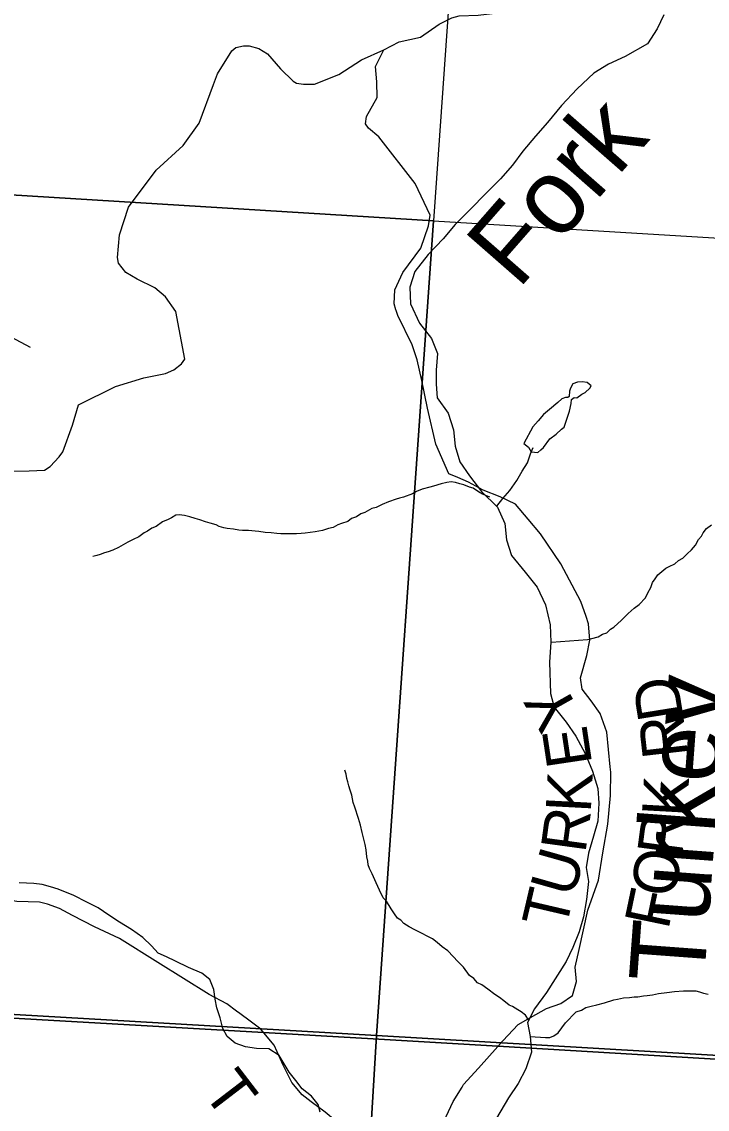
# Model space of a CAD drawing. Extents: x 0 to 34, y 0 to 22.
# Drawn here: x 7.274 to 8.137, y 16.183 to 17.554 of the extents above; entities that cross this region are included whole.
import ezdxf

# ---------------------------------------------------------------- set-up
doc = ezdxf.new("R2010")
doc.units = 0
for name, color, linetype in [('GM_X_Corporation', 7, 'Continuous'), ('GM_X_County_Road', 7, 'Continuous'), ('GM_X_Minor_Lake', 7, 'Continuous'), ('GM_X_Minor_River', 7, 'Continuous'), ('GM_X_Minor_River_Text', 7, 'Continuous'), ('GM_X_Township_Road', 7, 'Continuous'), ('GM_X_Township_Road_Text', 7, 'Continuous')]:
    doc.layers.add(name, color=color, linetype=linetype)

msp = doc.modelspace()

# ---------------------------------------------------------------- linework, layer by layer
at = {"layer": 'GM_X_Corporation'}
for points in [[(8.9, 16.2015), (8.9, 20.2763), (8.59, 20.3005), (8.3805, 20.3169), (8.0028, 20.34), (6.9032, 20.4198), (6.8961, 20.3303), (6.835, 19.4037), (6.824, 19.3005), (6.7876, 18.7583), (6.7629, 18.3924), (6.7536, 18.2991), (6.7043, 17.4985), (6.6962, 17.3669), (6.6852, 17.2401), (6.6249, 16.3344), (7.5782, 16.28), (7.7162, 16.2721), (7.873, 16.2628)], [(6.7676, 18.3985), (7.864, 18.3242), (7.7921, 17.3025), (6.6999, 17.3699), (6.7615, 18.3053)], [(8.9, 17.3437), (8.9, 18.2556), (7.864, 18.3242), (7.7921, 17.3025), (8.8926, 17.2358)], [(6.6999, 17.3699), (7.7921, 17.3025), (7.7202, 16.2762), (6.6272, 16.3394), (6.6918, 17.2464)], [(7.7921, 17.3025), (8.8926, 17.2358), (8.826, 16.2114), (7.7202, 16.2762)], [(5.4627, 14.1), (8.9, 14.1), (8.9, 16.2015), (7.873, 16.2628), (7.7162, 16.2721), (7.5782, 16.28), (6.6249, 16.3344), (6.6163, 16.2457), (5.9321, 16.289), (5.8351, 16.2952), (5.6497, 16.3069), (5.6022, 16.3258), (5.5809, 15.9822), (5.4893, 14.5091), (5.4833, 14.4122), (5.4763, 14.3006)], [(6.6272, 16.3394), (7.7202, 16.2762), (7.66, 15.265), (6.5568, 15.3381), (6.621, 16.2504)], [(7.7202, 16.2762), (8.826, 16.2114), (8.7674, 15.1938), (7.66, 15.265)]]:
    msp.add_lwpolyline(points, close=True, dxfattribs=at)
at = {"layer": 'GM_X_County_Road'}
for points in [[(7.5153, 17.4745), (7.5203, 17.488), (7.5383, 17.5171), (7.5434, 17.5211), (7.5527, 17.523), (7.5599, 17.5233), (7.5721, 17.5199), (7.5831, 17.5133), (7.5993, 17.4944), (7.6154, 17.4786), (7.6196, 17.4761), (7.6284, 17.4748), (7.6424, 17.475), (7.6731, 17.4871), (7.7014, 17.5056), (7.7298, 17.5182), (7.7491, 17.5284), (7.7756, 17.534), (7.7991, 17.5506), (7.8152, 17.5584), (7.8244, 17.561), (7.8484, 17.562), (7.866, 17.564)], [(7.2453, 16.9872), (7.2829, 16.9875), (7.3023, 16.9884), (7.3096, 16.993), (7.3209, 17.0055), (7.3253, 17.0115), (7.3375, 17.0454), (7.3449, 17.0709), (7.3918, 17.0941), (7.4274, 17.1047), (7.4548, 17.1103), (7.4653, 17.1149), (7.4746, 17.1224), (7.4789, 17.1284), (7.4678, 17.1883), (7.4546, 17.2069), (7.4413, 17.2181), (7.4188, 17.229), (7.4046, 17.2376), (7.3953, 17.2494), (7.3942, 17.2565), (7.3966, 17.285), (7.4081, 17.3201), (7.443, 17.3664), (7.477, 17.3975), (7.4972, 17.4258), (7.5153, 17.4745)]]:
    msp.add_lwpolyline(points, dxfattribs=at)
at = {"layer": 'GM_X_Minor_Lake'}
for points in [[(7.9635, 17.0628), (7.9654, 17.0726), (7.9658, 17.0775), (7.9692, 17.0802), (7.9726, 17.0798), (7.979, 17.0844), (7.9832, 17.0863), (7.9892, 17.092), (7.9907, 17.0946), (7.9858, 17.0988), (7.9794, 17.0999), (7.9733, 17.0995), (7.9676, 17.0973), (7.9646, 17.092), (7.9635, 17.0882), (7.9631, 17.0813), (7.9612, 17.0802), (7.9582, 17.0802), (7.9536, 17.0783), (7.9487, 17.0738), (7.9381, 17.065), (7.9305, 17.0586), (7.9241, 17.0506), (7.9173, 17.043), (7.9059, 17.0222), (7.9116, 17.0176), (7.9152, 17.0118)], [(7.9152, 17.0118), (7.9237, 17.0108), (7.9275, 17.0142), (7.9305, 17.0169), (7.9385, 17.0279), (7.9468, 17.034), (7.9532, 17.04), (7.9567, 17.0427), (7.9612, 17.0567), (7.9635, 17.0628)]]:
    msp.add_lwpolyline(points, dxfattribs=at)
at = {"layer": 'GM_X_Minor_River'}
for points in [[(7.2846, 17.1431), (7.2605, 17.1561), (7.2408, 17.1706), (7.2235, 17.1919), (7.2167, 17.2124), (7.216, 17.2329), (7.2123, 17.2557), (7.2033, 17.2739), (7.1882, 17.2944), (7.1671, 17.318), (7.1558, 17.3363), (7.1407, 17.3591), (7.1385, 17.3804), (7.1409, 17.4016), (7.1303, 17.4199), (7.1129, 17.4328), (7.1009, 17.4526), (7.0911, 17.4701), (7.0836, 17.4883), (7.07, 17.5142), (7.0572, 17.5332), (7.0452, 17.5545)], [(8.0823, 17.5622), (8.0739, 17.5447), (8.0617, 17.5258), (8.0336, 17.5099), (8.0124, 17.5001), (7.9942, 17.4888), (7.973, 17.4691), (7.9532, 17.4479), (7.9357, 17.4267), (7.9206, 17.4093), (7.9046, 17.3904), (7.8917, 17.3729), (7.8765, 17.3555), (7.8583, 17.3374), (7.8385, 17.3169), (7.8195, 17.298), (7.8043, 17.2798), (7.7854, 17.2601), (7.7686, 17.2389), (7.7625, 17.2192), (7.7632, 17.198), (7.7745, 17.1737), (7.7896, 17.1546), (7.7971, 17.1356), (7.7955, 17.1144), (7.7955, 17.0969), (7.7969, 17.0795), (7.8105, 17.0605), (7.8172, 17.0392), (7.8194, 17.0187), (7.8254, 16.999), (7.8375, 16.9815), (7.8526, 16.9617), (7.8729, 16.9419), (7.882, 16.9214), (7.8842, 16.9009), (7.8902, 16.8812), (7.9075, 16.8599), (7.9226, 16.8409), (7.9331, 16.8188), (7.9391, 16.7938), (7.9398, 16.7718), (7.9382, 16.7467), (7.9396, 16.7073), (7.9441, 16.6898), (7.9591, 16.6708), (7.9712, 16.6533), (7.9833, 16.6313), (7.9923, 16.6093), (7.999, 16.5872), (8.0005, 16.569), (7.9989, 16.5463), (7.9935, 16.5273), (7.9874, 16.5061), (7.9843, 16.4879), (7.9873, 16.4704), (7.985, 16.4477), (7.9811, 16.4257), (7.9757, 16.4068), (7.9674, 16.3871), (7.959, 16.3696), (7.9346, 16.3302), (7.9194, 16.3098), (7.9103, 16.2924), (7.914, 16.2749), (7.9155, 16.2552), (7.9086, 16.234), (7.8987, 16.2158), (7.8865, 16.1976), (7.8713, 16.1719)], [(7.8717, 16.9432), (7.8794, 16.9528), (7.8881, 16.9631), (7.8972, 16.9756), (7.9037, 16.9873), (7.9105, 16.9976), (7.9143, 17.0089), (7.9177, 17.0169)], [(7.8632, 16.9547), (7.8579, 16.9567), (7.8538, 16.9583), (7.8489, 16.9614), (7.8422, 16.9657), (7.8373, 16.967), (7.8305, 16.9701), (7.8252, 16.9713), (7.82, 16.973), (7.8143, 16.9738), (7.809, 16.9731), (7.8018, 16.9714), (7.7922, 16.9685), (7.7877, 16.967), (7.7778, 16.9645), (7.7709, 16.9616), (7.7655, 16.9587), (7.7545, 16.9543), (7.7492, 16.9532), (7.745, 16.9518), (7.7354, 16.9485), (7.7274, 16.9452), (7.7198, 16.9416), (7.7145, 16.9401), (7.7057, 16.935), (7.7007, 16.9335), (7.695, 16.9298), (7.6889, 16.9277), (7.6843, 16.9239), (7.6763, 16.9214), (7.6717, 16.9196), (7.6659, 16.9163), (7.6599, 16.9152), (7.6522, 16.9127), (7.6431, 16.9109), (7.6306, 16.9093), (7.6253, 16.9086), (7.6196, 16.9083), (7.6094, 16.9081), (7.5999, 16.9083), (7.595, 16.9087), (7.5878, 16.9096), (7.5802, 16.9101), (7.5723, 16.9114), (7.5674, 16.9115), (7.5591, 16.9124), (7.5515, 16.9125), (7.547, 16.9129), (7.5402, 16.9142), (7.5322, 16.9151), (7.5281, 16.9159), (7.5224, 16.9175), (7.5183, 16.9195), (7.5107, 16.9219), (7.5051, 16.9235), (7.4979, 16.9259), (7.4919, 16.9276), (7.4855, 16.9299), (7.4787, 16.9316), (7.4719, 16.9321), (7.4677, 16.9318), (7.4624, 16.9284), (7.4582, 16.9262), (7.4509, 16.9233), (7.4429, 16.9177), (7.4375, 16.9155), (7.4322, 16.9115), (7.428, 16.9096), (7.4211, 16.9044), (7.4138, 16.9011), (7.4073, 16.8978), (7.4012, 16.8945), (7.3954, 16.8912), (7.3882, 16.8879), (7.3825, 16.8857), (7.3779, 16.8843), (7.3726, 16.8821), (7.368, 16.881), (7.363, 16.8799)], [(7.9406, 16.7718), (7.9862, 16.7752), (7.9915, 16.7763), (7.9995, 16.7784), (8.0049, 16.7818), (8.0102, 16.7836), (8.0152, 16.788), (8.0194, 16.7906), (8.0244, 16.7955), (8.0286, 16.7992), (8.0329, 16.8037), (8.0371, 16.8078), (8.0448, 16.8145), (8.051, 16.8194), (8.0591, 16.8276), (8.0622, 16.834), (8.0657, 16.8408), (8.0681, 16.8468), (8.0712, 16.8517), (8.0747, 16.8566), (8.0797, 16.8607), (8.0847, 16.8651), (8.0889, 16.867), (8.0962, 16.8703), (8.1008, 16.8748), (8.1062, 16.8777), (8.1116, 16.8833), (8.1169, 16.8882), (8.122, 16.8942), (8.1259, 16.9013), (8.1298, 16.9054), (8.1317, 16.9096), (8.136, 16.9152), (8.1421, 16.9197)], [(7.9119, 16.2958), (7.9078, 16.302), (7.9026, 16.3059), (7.8984, 16.3087), (7.8917, 16.3126), (7.8876, 16.3145), (7.8808, 16.32), (7.8752, 16.3242), (7.8692, 16.3278), (7.8606, 16.3344), (7.8528, 16.3402), (7.8475, 16.3426), (7.8431, 16.348), (7.8375, 16.3519), (7.8301, 16.3622), (7.823, 16.3692), (7.81, 16.3827), (7.8029, 16.3881), (7.7969, 16.3932), (7.7909, 16.3978), (7.7842, 16.4014), (7.7778, 16.4049), (7.7688, 16.4092), (7.7616, 16.4131), (7.7549, 16.4171), (7.7508, 16.4213), (7.7467, 16.424), (7.743, 16.4294), (7.7389, 16.4359), (7.733, 16.4455), (7.7286, 16.4498), (7.7242, 16.4594), (7.7198, 16.4686), (7.7147, 16.48), (7.7114, 16.4866), (7.71, 16.4911), (7.7093, 16.4957), (7.7083, 16.5014), (7.7073, 16.5102), (7.7059, 16.5167), (7.7041, 16.5254), (7.7024, 16.5319), (7.7003, 16.5414), (7.6978, 16.5498), (7.696, 16.5548), (7.6949, 16.559), (7.6931, 16.564), (7.6909, 16.5697), (7.6892, 16.5789), (7.687, 16.5854), (7.6856, 16.5907), (7.6842, 16.5957), (7.6831, 16.6002), (7.6821, 16.6056), (7.6806, 16.6105)], [(7.6495, 16.1797), (7.6468, 16.1892), (7.6385, 16.1998), (7.6268, 16.2089), (7.6188, 16.2195), (7.6105, 16.2301), (7.5977, 16.251), (7.5848, 16.2593), (7.5693, 16.2597), (7.5556, 16.262), (7.5424, 16.2665), (7.5322, 16.2748), (7.5269, 16.2851), (7.5235, 16.2983), (7.5193, 16.3112), (7.5171, 16.3218), (7.5155, 16.334), (7.5103, 16.3468), (7.5004, 16.3548), (7.4838, 16.362), (7.4671, 16.3699), (7.4561, 16.3753), (7.4455, 16.3798), (7.4372, 16.3893), (7.4262, 16.3995), (7.4119, 16.4097), (7.3967, 16.4188), (7.3831, 16.4279), (7.3699, 16.437), (7.3555, 16.4442), (7.3392, 16.4525), (7.3195, 16.4605), (7.3097, 16.4635), (7.2995, 16.4666), (7.2889, 16.4677), (7.2703, 16.4685)], [(7.914, 16.2749), (7.933, 16.2735), (7.9387, 16.2738), (7.9437, 16.2756), (7.9491, 16.2797), (7.9537, 16.2857), (7.9584, 16.2921), (7.963, 16.2966), (7.9669, 16.3011), (7.9719, 16.3059), (7.9783, 16.3081), (7.9841, 16.3114), (7.9906, 16.3132), (7.9978, 16.315), (8.0073, 16.3175), (8.0191, 16.3211), (8.0237, 16.3221), (8.0313, 16.3235), (8.0389, 16.3242), (8.0449, 16.3248), (8.0495, 16.3251), (8.0567, 16.3261), (8.0612, 16.3264), (8.0677, 16.3275), (8.0753, 16.3289), (8.0859, 16.3302), (8.0958, 16.3316), (8.1068, 16.3325), (8.1148, 16.3324), (8.1223, 16.3323), (8.1269, 16.3314), (8.1321, 16.3294), (8.1378, 16.3282)]]:
    msp.add_lwpolyline(points, dxfattribs=at)
at = {"layer": 'GM_X_Township_Road'}
for points in [[(7.7449, 17.1907), (7.7425, 17.1979), (7.7436, 17.2158), (7.7535, 17.2375), (7.776, 17.2682), (7.7858, 17.2964), (7.7881, 17.3097), (7.7692, 17.3499), (7.7233, 17.4085), (7.7104, 17.4195), (7.7066, 17.4248), (7.7077, 17.4343), (7.721, 17.4583), (7.7207, 17.478), (7.7192, 17.497), (7.7298, 17.5182)], [(7.9843, 16.8041), (7.9776, 16.8229), (7.9526, 16.8707), (7.9268, 16.9084), (7.9113, 16.9266), (7.8953, 16.9456), (7.876, 16.9551), (7.8547, 16.9635), (7.8361, 16.9734), (7.8228, 16.9794), (7.8114, 16.984), (7.7951, 17.0212), (7.7845, 17.0668), (7.7773, 17.1014), (7.7717, 17.1276), (7.7652, 17.1463), (7.7474, 17.1835), (7.7452, 17.1898), (7.7449, 17.1907)], [(8.0148, 16.6145), (8.0105, 16.6584), (8.0022, 16.6819), (7.9905, 16.6979), (7.9794, 16.7127), (7.9772, 16.7268), (7.9852, 16.7549), (7.989, 16.7742), (7.9875, 16.7951), (7.9843, 16.8041)], [(7.8281, 16.2111), (7.8301, 16.2144), (7.8488, 16.2349), (7.8732, 16.2623), (7.8796, 16.2695), (7.8986, 16.29), (7.9142, 16.2987), (7.9343, 16.3101), (7.9525, 16.3165), (7.967, 16.3264), (7.9723, 16.3442), (7.9704, 16.3621), (7.9754, 16.3845), (7.9864, 16.4339), (8.0001, 16.4719), (8.0055, 16.5064), (8.0116, 16.5425), (8.015, 16.5786), (8.0154, 16.6078), (8.0148, 16.6145)], [(7.5441, 16.3069), (7.5321, 16.3159), (7.5097, 16.3277), (7.4448, 16.3683), (7.3966, 16.3984), (7.3654, 16.4132), (7.3377, 16.4272), (7.321, 16.436), (7.3062, 16.4417), (7.2959, 16.444), (7.2675, 16.4451), (7.2207, 16.4531)], [(7.7559, 16.1046), (7.7328, 16.1199), (7.7028, 16.1385), (7.6858, 16.1514), (7.6687, 16.1685), (7.6558, 16.1795), (7.6379, 16.1924), (7.6266, 16.2015), (7.6137, 16.2171), (7.603, 16.2388), (7.5913, 16.2642), (7.5784, 16.2795), (7.5746, 16.284), (7.5611, 16.2941), (7.5484, 16.3037), (7.5441, 16.3069)], [(7.706, 15.87), (7.7091, 15.9026), (7.7148, 15.9478), (7.719, 15.9721), (7.7285, 15.9934), (7.7411, 16.0135), (7.7476, 16.0374), (7.7483, 16.064), (7.7484, 16.0849), (7.7537, 16.1016), (7.7559, 16.1046), (7.7663, 16.1187), (7.7773, 16.1309), (7.7921, 16.1491), (7.805, 16.1677), (7.8168, 16.1931), (7.8281, 16.2111)]]:
    msp.add_lwpolyline(points, dxfattribs=at)

# ---------------------------------------------------------------- texts
at = {"layer": 'GM_X_Minor_River_Text'}
for s, height, rotation, p in [('Fork', 0.09473, 48.7821, (7.8987, 17.215)), ('Turkey', 0.09471, 85.7613, (8.1325, 16.3401))]:
    msp.add_text(s, height=height, rotation=rotation, dxfattribs=at).set_placement(p)
at = {"layer": 'GM_X_Township_Road_Text'}
for s, rotation, p in [('D', 99.1344, (8.1069, 16.6777)), ('Y', 119.4879, (7.9785, 16.6814)), ('R', 96.5551, (8.1126, 16.6286)), ('E', 98.5487, (7.9921, 16.6184)), ('K', 87.0193, (7.9901, 16.5562)), ('K', 86.8179, (8.1112, 16.5507)), ('R', 82.2469, (7.9833, 16.5049)), ('R', 82.4873, (8.1047, 16.4997)), ('U', 74.1872, (7.9679, 16.4484)), ('O', 80.5916, (8.0962, 16.4484)), ('T', 76.8304, (7.9584, 16.4077)), ('F', 78.1559, (8.0878, 16.4083)), ('T', 307.4751, (7.5, 16.2047))]:
    msp.add_text(s, height=0.0568, rotation=rotation, dxfattribs=at).set_placement(p)

doc.saveas('drawing.dxf')
